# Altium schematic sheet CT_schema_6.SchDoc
size 298 x 258 mm
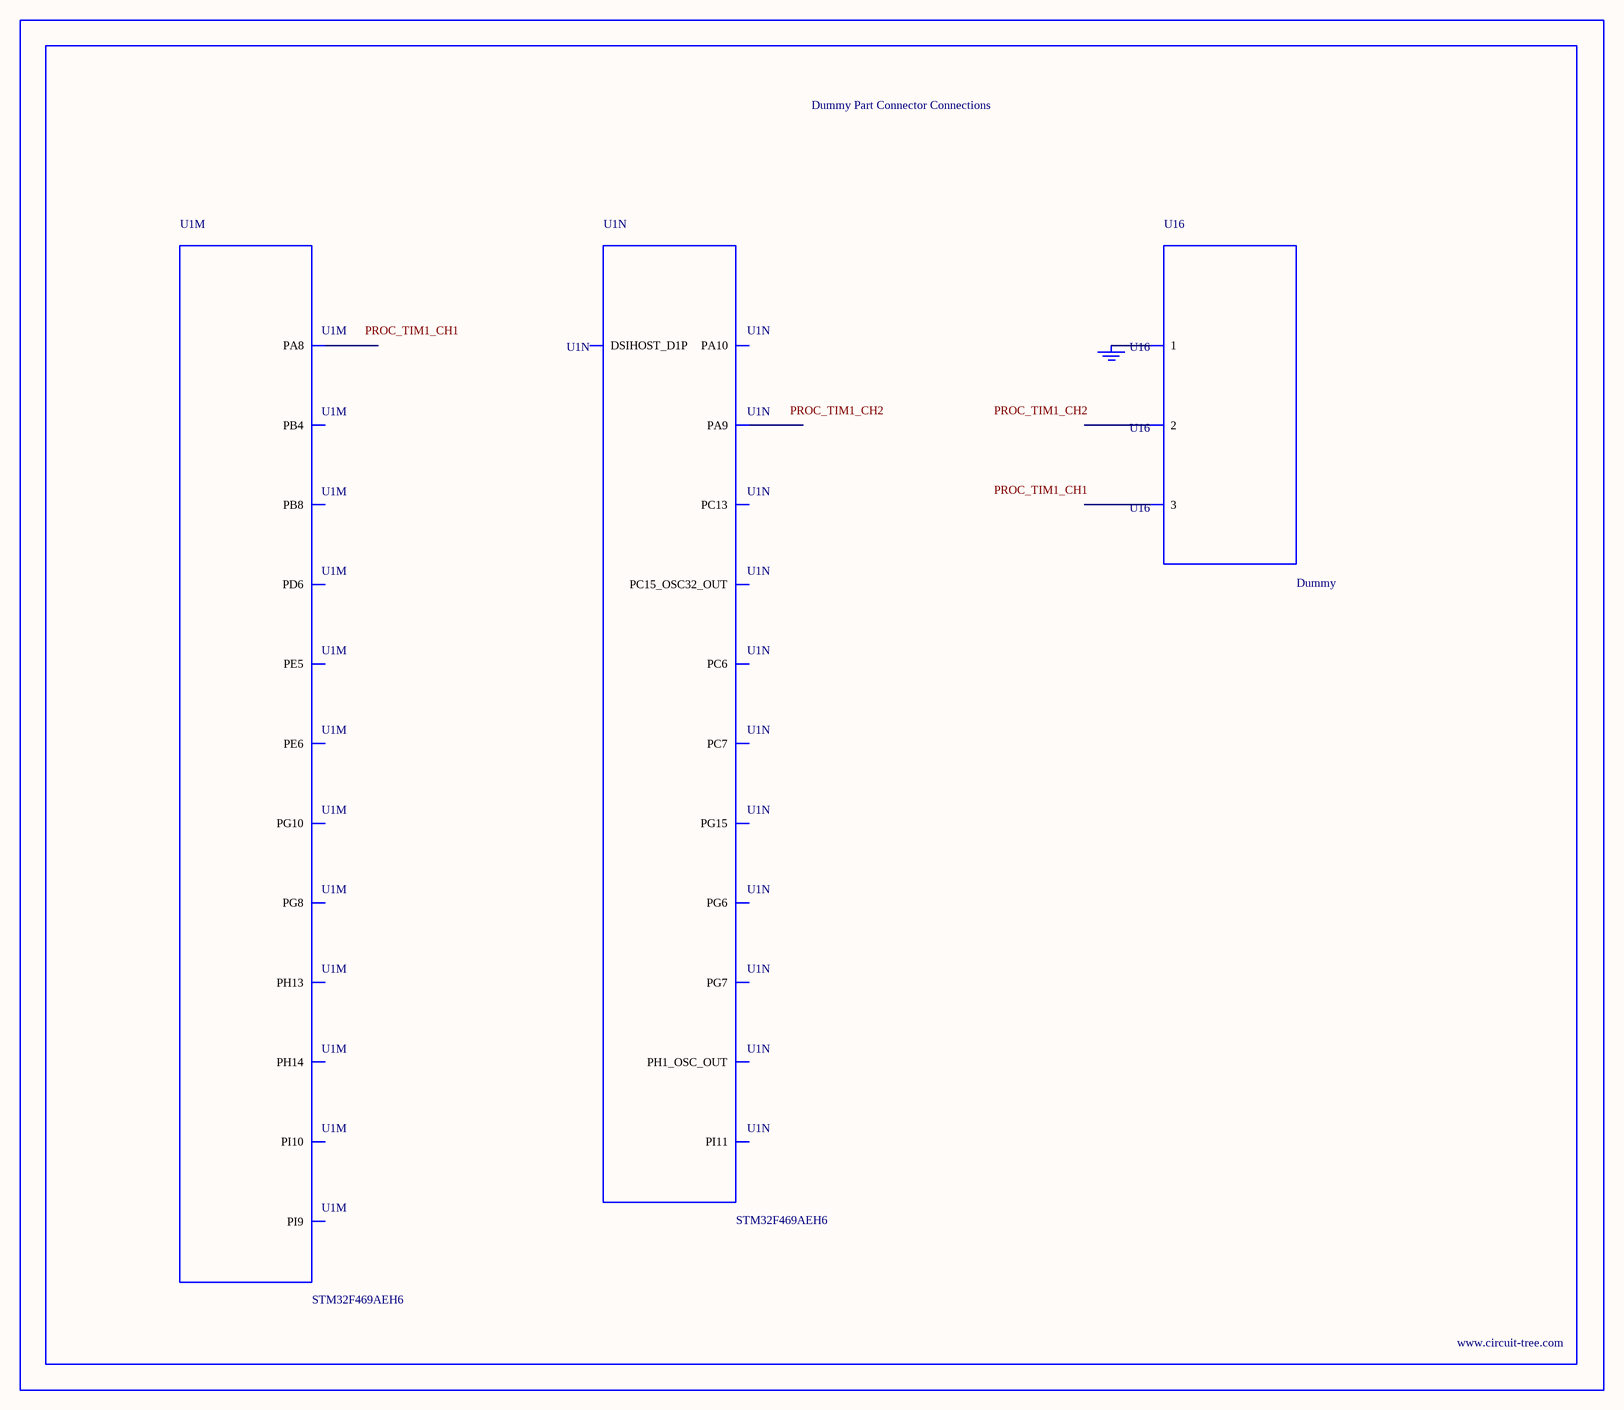
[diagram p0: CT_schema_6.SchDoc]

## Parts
BORDER5  (no value)
GND_INSTANCE_5_0  (no value)
U1  STM32F469AEH6  [UFBGA169]  (parts M,N of 14)
U16  Dummy  [DUMMY_PACKAGE_186]

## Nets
NetGND_INSTANCE_5_0_0: GND_INSTANCE_5_0.0(GND) U16.1

Not connected (* = marked no-connect by the designer): U1 C13(PH14) D1(PE5) D2(PE6) D4(PB8) D6(PB4) D7(PD6) D8(PA8) D9(PH13) D13(PG8) E2(PI9) E4(PI10) E7(PG10) E8(PA9) E9(PA10) E11(PG7) F1(PC15_OSC32_OUT) F2(PI11) F6(PG15) F9(PC6) F10(PC7) F11(PG6) G1(PH1_OSC_OUT) G4(PC13) G12(DSIHOST_D1P); U16 2 3

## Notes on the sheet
- Labels drawn without touching a wire or pin: PROC_TIM1_CH1, PROC_TIM1_CH2

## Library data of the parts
BORDER5 = BORDER_PAGE5
GND_INSTANCE_5_0 = GND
